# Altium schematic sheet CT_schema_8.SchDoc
size 255 x 245 mm
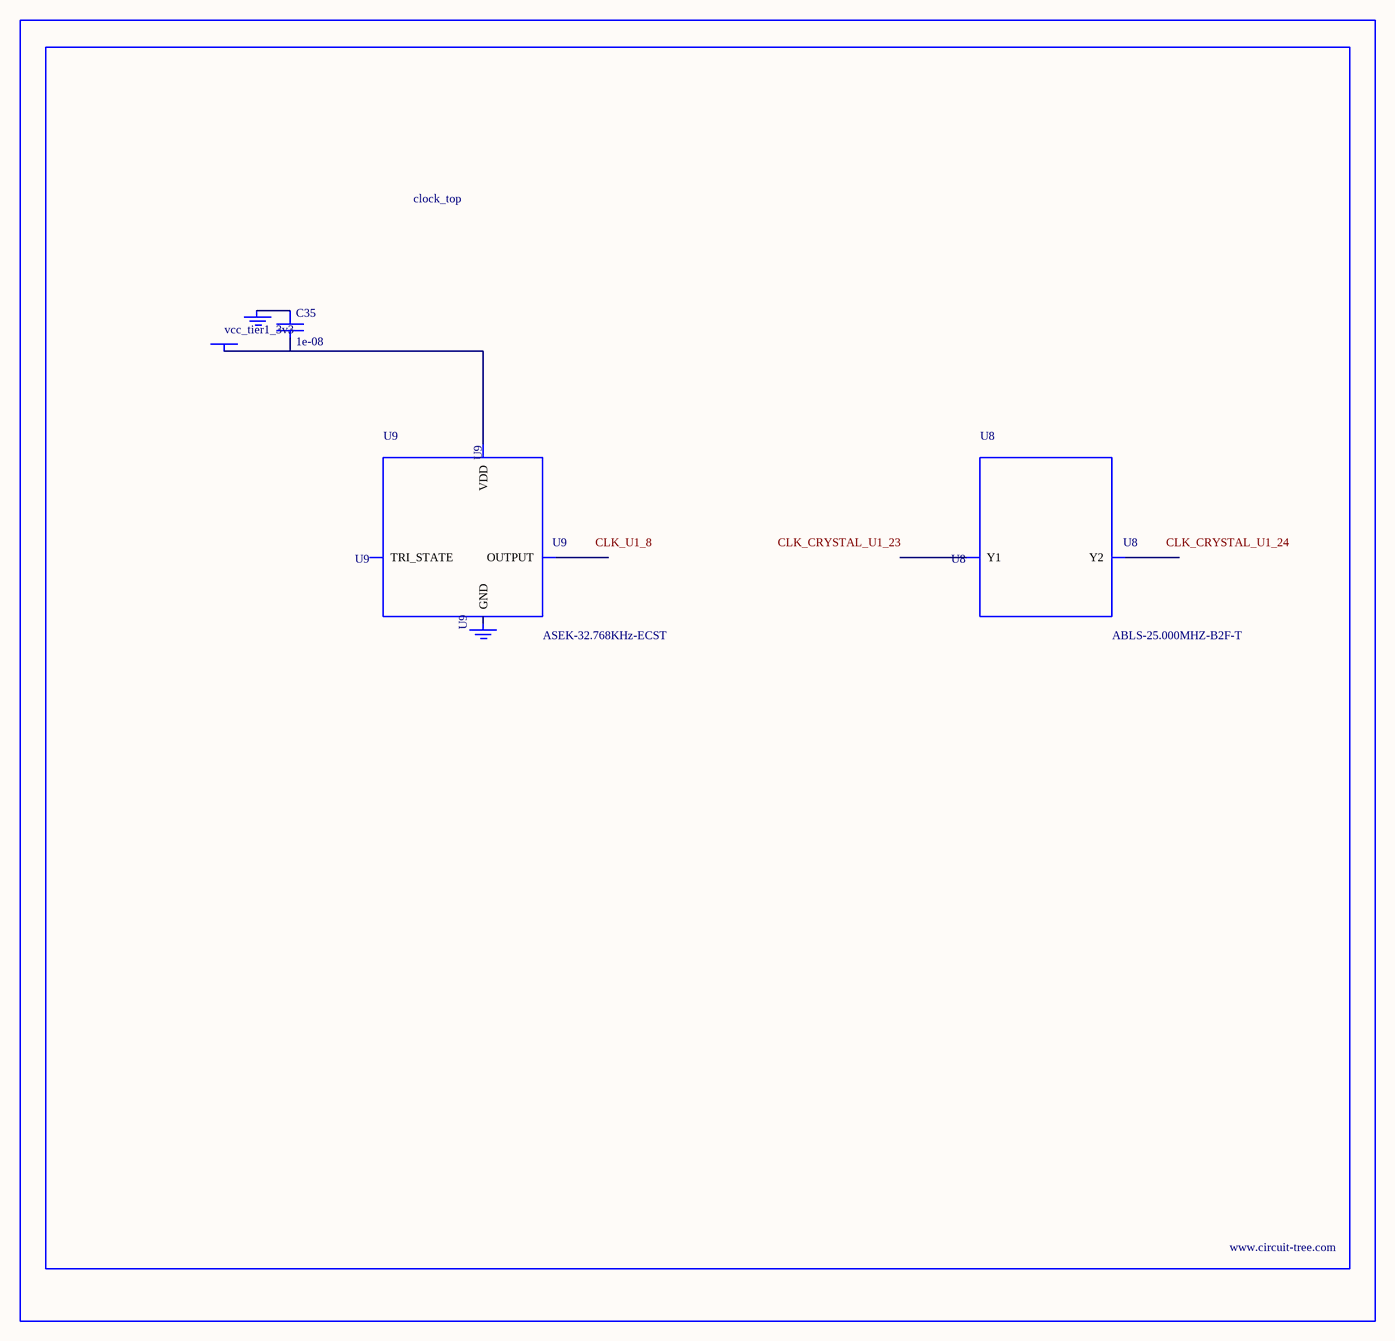
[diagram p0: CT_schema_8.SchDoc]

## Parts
BORDER7  (no value)
C35  1e-08  [C0402]
GND_INSTANCE_7_0  (no value)
GND_INSTANCE_7_1  (no value)
POWER_INSTANCE_7_0  vcc_tier1_3v3
U8  ABLS-25.000MHZ-B2F-T  [ABLS-25.000MHZ-B2F-T]
U9  ASEK-32.768KHz-ECST  [ASEK]

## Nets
NetC35_1: C35.1 GND_INSTANCE_7_0.0(GND)
NetC35_2: C35.2 POWER_INSTANCE_7_0.0(PWR) U9.4(VDD)

Not connected (* = marked no-connect by the designer): GND_INSTANCE_7_1 0(GND); U8 1(Y1) 2(Y2); U9 1(TRI_STATE) 2(GND) 3(OUTPUT)

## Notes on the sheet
- Labels drawn without touching a wire or pin: CLK_CRYSTAL_U1_23, CLK_CRYSTAL_U1_24, CLK_U1_8

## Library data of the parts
BORDER7 = BORDER_PAGE7
C35 = C0402C103K3RAC
GND_INSTANCE_7_0 GND_INSTANCE_7_1 = GND
POWER_INSTANCE_7_0 = PWR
